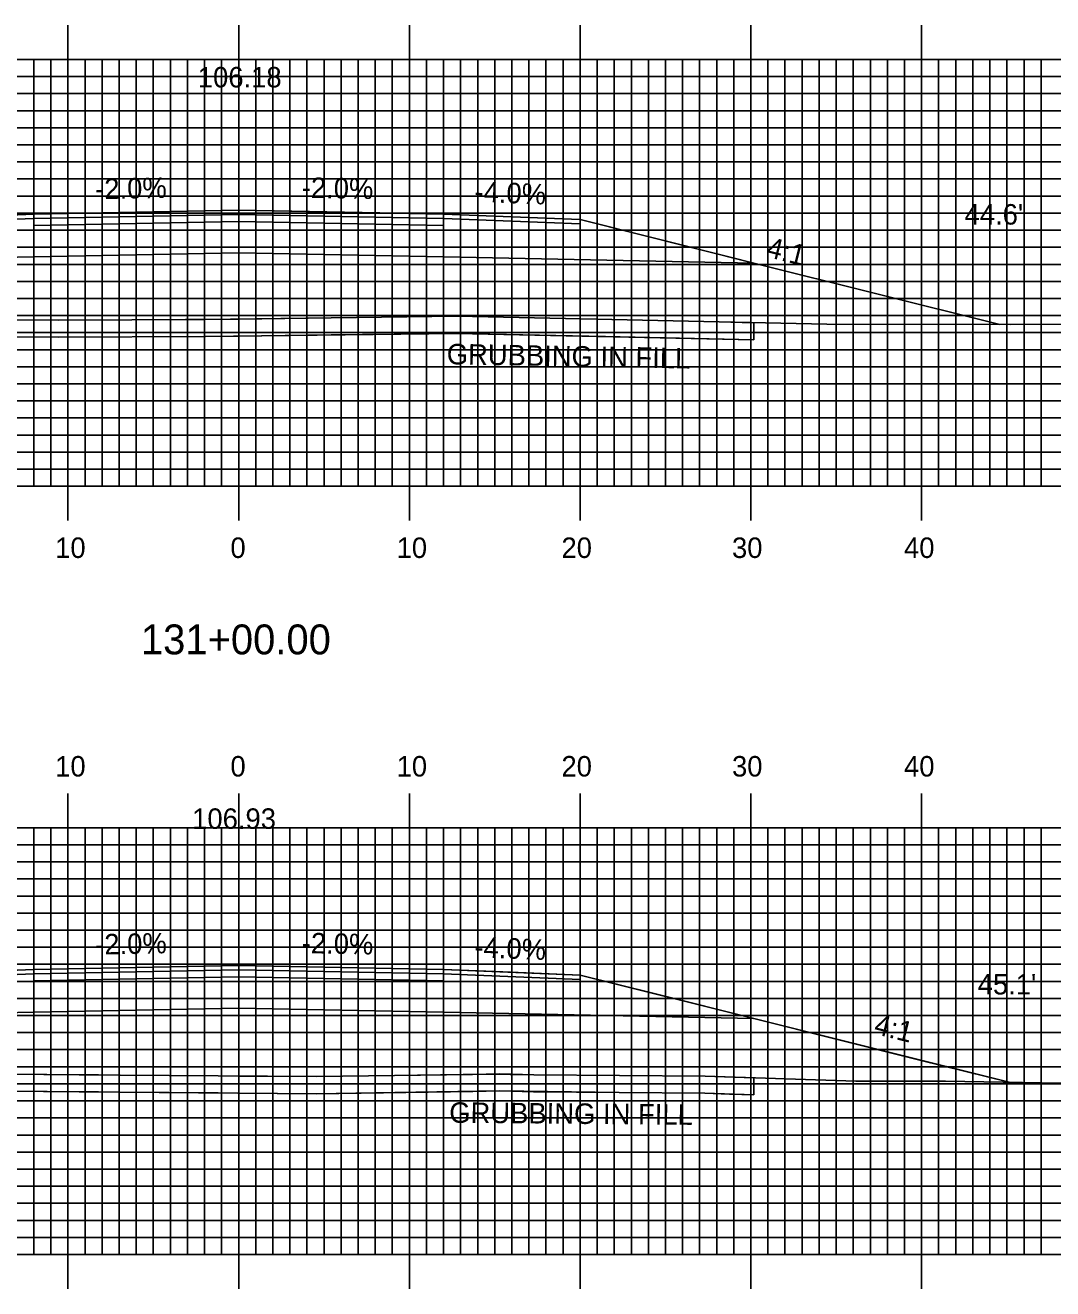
# Model space of a CAD drawing. Extents: x 1773990 to 1774333, y 442591 to 442811.
# Drawn here: x 1774143.2 to 1774203.3, y 442686.7 to 442760.7 of the extents above; entities that cross this region are included whole.
import ezdxf

# ---------------------------------------------------------------- set-up
doc = ezdxf.new("R2010")
doc.units = 0
for name, color, linetype in [('ANNOTATION', 7, 'Continuous'), ('D_Roadway_Centerline', 7, 'Continuous'), ('D_Roadway_Centerline_Text', 7, 'Continuous'), ('D_Roadway_Edge_Shoulder', 7, 'Continuous'), ('D_Roadway_Edge_TW', 7, 'Continuous'), ('D_Roadway_Pavement', 7, 'Continuous'), ('D_Roadway_SlopeLines', 7, 'Continuous'), ('D_Roadway_SubGrade', 7, 'Continuous'), ('D_Text_Standard', 7, 'Continuous'), ('GRUBBING IN FILL', 7, 'Continuous'), ('H_V ANNOTATION', 7, 'Continuous'), ('MAJOR', 7, 'Continuous'), ('MINOR', 7, 'Continuous'), ('S_Roadway_Centerline', 7, 'Continuous')]:
    doc.layers.add(name, color=color, linetype=linetype)

msp = doc.modelspace()

# ---------------------------------------------------------------- linework, layer by layer
at = {"layer": 'D_Roadway_Centerline'}
for points in [[(1774113.41, 442743.721), (1774123.659, 442746.284), (1774125.485, 442746.74), (1774135.659, 442749.284), (1774139.864, 442749.452), (1774143.659, 442749.604), (1774145.7, 442749.645), (1774155.657, 442749.844), (1774155.659, 442749.844), (1774164.958, 442749.658), (1774167.659, 442749.604), (1774175.659, 442749.284), (1774184.368, 442747.107), (1774185.833, 442746.74), (1774200.249, 442743.136)], [(1774112.312, 442699.568), (1774123.87, 442702.458), (1774133.89, 442704.963), (1774138.828, 442705.161), (1774143.659, 442705.354), (1774143.66, 442705.354), (1774155.659, 442705.594), (1774167.659, 442705.354), (1774171.137, 442705.215), (1774175.659, 442705.034), (1774180.146, 442703.912), (1774185.833, 442702.49), (1774195.567, 442700.056), (1774200.784, 442698.752)]]:
    msp.add_lwpolyline(points, dxfattribs=at)
at = {"layer": 'D_Roadway_Edge_Shoulder'}
for points in [[(1774143.659, 442749.604), (1774135.659, 442749.284), (1774135.659, 442749.034), (1774143.659, 442749.354)], [(1774167.659, 442749.604), (1774175.659, 442749.284), (1774175.659, 442749.034), (1774167.659, 442749.354)], [(1774143.659, 442705.354), (1774133.89, 442704.963), (1774133.89, 442704.713), (1774143.659, 442705.104)], [(1774167.659, 442705.354), (1774175.659, 442705.034), (1774175.659, 442704.784), (1774167.659, 442705.104)]]:
    msp.add_lwpolyline(points, close=True, dxfattribs=at)
at = {"layer": 'D_Roadway_Edge_TW'}
for points in [[(1774143.659, 442749.354), (1774143.659, 442749.604), (1774155.659, 442749.844), (1774167.659, 442749.604), (1774167.659, 442749.354), (1774155.659, 442749.594)], [(1774143.659, 442705.104), (1774143.659, 442705.354), (1774155.659, 442705.594), (1774167.659, 442705.354), (1774167.659, 442705.104), (1774155.659, 442705.344)]]:
    msp.add_lwpolyline(points, close=True, dxfattribs=at)
at = {"layer": 'D_Roadway_Pavement'}
for points in [[(1774143.659, 442748.937), (1774143.659, 442749.354), (1774155.659, 442749.594), (1774167.659, 442749.354), (1774167.659, 442748.937), (1774155.659, 442749.177)], [(1774143.659, 442704.687), (1774143.659, 442705.104), (1774155.659, 442705.344), (1774167.659, 442705.104), (1774167.659, 442704.687), (1774155.659, 442704.927)]]:
    msp.add_lwpolyline(points, close=True, dxfattribs=at)
at = {"layer": 'D_Roadway_SlopeLines'}
for points in [[(1774175.659, 442749.284), (1774185.833, 442746.74), (1774200.249, 442743.136)], [(1774175.659, 442705.034), (1774185.833, 442702.49), (1774200.784, 442698.752)]]:
    msp.add_lwpolyline(points, dxfattribs=at)
at = {"layer": 'D_Roadway_SubGrade'}
for points in [[(1774143.659, 442747.104), (1774125.485, 442746.74), (1774135.659, 442749.284), (1774135.659, 442749.034), (1774143.659, 442749.354), (1774155.659, 442749.594), (1774167.659, 442749.354), (1774175.659, 442749.034), (1774175.659, 442749.284), (1774185.833, 442746.74), (1774167.659, 442747.104), (1774155.659, 442747.344)], [(1774143.659, 442702.854), (1774123.87, 442702.458), (1774133.89, 442704.963), (1774133.89, 442704.713), (1774143.659, 442705.104), (1774155.659, 442705.344), (1774167.659, 442705.104), (1774175.659, 442704.784), (1774175.659, 442705.034), (1774185.833, 442702.49), (1774167.659, 442702.854), (1774155.659, 442703.094)]]:
    msp.add_lwpolyline(points, close=True, dxfattribs=at)
at = {"layer": 'GRUBBING IN FILL'}
for p, q in [((1774185.833, 442743.248), (1774185.833, 442742.248)), ((1774185.833, 442743.248), (1774185.833, 442742.248)), ((1774185.833, 442699.02), (1774185.833, 442698.019)), ((1774185.833, 442699.02), (1774185.833, 442698.019))]:
    msp.add_line(p, q, dxfattribs=at)
for points in [[(1774125.485, 442743.49), (1774130.474, 442743.468), (1774137.786, 442743.435), (1774145.098, 442743.402), (1774149.402, 442743.416), (1774155.659, 442743.456), (1774155.659, 442742.456), (1774153.713, 442742.43), (1774145.097, 442742.402), (1774135.291, 442742.446), (1774125.485, 442742.49)], [(1774125.485, 442743.49), (1774130.474, 442743.468), (1774137.786, 442743.435), (1774145.098, 442743.402), (1774149.402, 442743.416), (1774155.659, 442743.456), (1774155.659, 442742.456), (1774153.713, 442742.43), (1774145.097, 442742.402), (1774135.291, 442742.446), (1774125.485, 442742.49)], [(1774155.659, 442743.456), (1774161.077, 442743.527), (1774168.448, 442743.624), (1774172.978, 442743.526), (1774177.508, 442743.428), (1774183.813, 442743.292), (1774185.833, 442743.248), (1774185.833, 442742.248), (1774177.139, 442742.436), (1774168.444, 442742.624), (1774161.079, 442742.527), (1774155.659, 442742.456)], [(1774155.659, 442743.456), (1774161.077, 442743.527), (1774168.448, 442743.624), (1774172.978, 442743.526), (1774177.508, 442743.428), (1774183.813, 442743.292), (1774185.833, 442743.248), (1774185.833, 442742.248), (1774177.139, 442742.436), (1774168.444, 442742.624), (1774161.079, 442742.527), (1774155.659, 442742.456)], [(1774125.485, 442699.396), (1774135.923, 442699.291), (1774146.312, 442699.187), (1774148.708, 442699.175), (1774154.465, 442699.129), (1774155.659, 442699.119), (1774155.659, 442698.119), (1774154.463, 442698.129), (1774148.7, 442698.175), (1774135.896, 442698.291), (1774125.485, 442698.396)], [(1774155.659, 442699.119), (1774160.222, 442699.083), (1774164.789, 442699.15), (1774170.158, 442699.238), (1774172.955, 442699.185), (1774177.971, 442699.15), (1774182.987, 442699.114), (1774185.833, 442699.02), (1774185.833, 442698.019), (1774184.4, 442698.067), (1774182.967, 442698.114), (1774177.95, 442698.15), (1774170.955, 442698.257), (1774164.8, 442698.15), (1774160.225, 442698.083), (1774155.659, 442698.119)], [(1774155.659, 442699.119), (1774160.222, 442699.083), (1774164.789, 442699.15), (1774170.158, 442699.238), (1774172.955, 442699.185), (1774177.971, 442699.15), (1774182.987, 442699.114), (1774185.833, 442699.02), (1774185.833, 442698.019), (1774184.4, 442698.067), (1774182.967, 442698.114), (1774177.95, 442698.15), (1774170.955, 442698.257), (1774164.8, 442698.15), (1774160.225, 442698.083), (1774155.659, 442698.119)]]:
    msp.add_lwpolyline(points, close=True, dxfattribs=at)
for points in [[(1774125.485, 442742.49), (1774145.097, 442742.402), (1774153.713, 442742.43), (1774168.444, 442742.624), (1774185.833, 442742.248)], [(1774125.485, 442742.49), (1774145.097, 442742.402), (1774153.713, 442742.43), (1774168.444, 442742.624), (1774185.833, 442742.248)], [(1774125.485, 442699.396), (1774135.923, 442699.291), (1774146.312, 442699.187), (1774148.708, 442699.175), (1774154.465, 442699.129), (1774155.659, 442699.119), (1774155.659, 442698.119), (1774154.463, 442698.129), (1774148.7, 442698.175), (1774135.896, 442698.291), (1774125.485, 442698.396)], [(1774125.485, 442698.396), (1774146.307, 442698.187), (1774147.443, 442698.186), (1774148.7, 442698.175), (1774160.225, 442698.083), (1774169.375, 442698.218), (1774170.955, 442698.257), (1774172.934, 442698.185), (1774182.967, 442698.114), (1774185.833, 442698.019)], [(1774125.485, 442698.396), (1774146.307, 442698.187), (1774147.443, 442698.186), (1774148.7, 442698.175), (1774160.225, 442698.083), (1774169.375, 442698.218), (1774170.955, 442698.257), (1774172.934, 442698.185), (1774182.967, 442698.114), (1774185.833, 442698.019)]]:
    msp.add_lwpolyline(points, dxfattribs=at)
at = {"layer": 'MAJOR'}
for p, q in [((1774145.659, 442760.669), (1774145.659, 442758.665)), ((1774155.659, 442760.669), (1774155.659, 442758.665)), ((1774165.659, 442760.669), (1774165.659, 442758.665)), ((1774175.659, 442760.669), (1774175.659, 442758.665)), ((1774185.659, 442760.669), (1774185.659, 442758.665)), ((1774195.659, 442760.669), (1774195.659, 442758.665)), ((1774015.659, 442758.665), (1774295.659, 442758.665)), ((1774015.659, 442758.665), (1774295.659, 442758.665)), ((1774145.659, 442733.665), (1774145.659, 442758.665)), ((1774155.659, 442733.665), (1774155.659, 442758.665)), ((1774165.659, 442733.665), (1774165.659, 442758.665)), ((1774175.659, 442733.665), (1774175.659, 442758.665)), ((1774185.659, 442733.665), (1774185.659, 442758.665)), ((1774195.659, 442733.665), (1774195.659, 442758.665)), ((1774015.659, 442753.665), (1774295.659, 442753.665)), ((1774015.659, 442748.665), (1774295.659, 442748.665)), ((1774015.659, 442743.665), (1774295.659, 442743.665)), ((1774015.659, 442738.665), (1774295.659, 442738.665)), ((1774015.659, 442733.665), (1774295.659, 442733.665)), ((1774015.659, 442733.665), (1774295.659, 442733.665)), ((1774145.659, 442731.661), (1774145.659, 442733.665)), ((1774155.659, 442731.661), (1774155.659, 442733.665)), ((1774165.659, 442731.661), (1774165.659, 442733.665)), ((1774175.659, 442731.661), (1774175.659, 442733.665)), ((1774185.659, 442731.661), (1774185.659, 442733.665)), ((1774195.659, 442731.661), (1774195.659, 442733.665)), ((1774145.659, 442715.669), (1774145.659, 442713.665)), ((1774155.659, 442715.669), (1774155.659, 442713.665)), ((1774165.659, 442715.669), (1774165.659, 442713.665)), ((1774175.659, 442715.669), (1774175.659, 442713.665)), ((1774185.659, 442715.669), (1774185.659, 442713.665)), ((1774195.659, 442715.669), (1774195.659, 442713.665)), ((1774015.659, 442713.665), (1774295.659, 442713.665)), ((1774015.659, 442713.665), (1774295.659, 442713.665)), ((1774145.659, 442688.665), (1774145.659, 442713.665)), ((1774155.659, 442688.665), (1774155.659, 442713.665)), ((1774165.659, 442688.665), (1774165.659, 442713.665)), ((1774175.659, 442688.665), (1774175.659, 442713.665)), ((1774185.659, 442688.665), (1774185.659, 442713.665)), ((1774195.659, 442688.665), (1774195.659, 442713.665)), ((1774015.659, 442708.665), (1774295.659, 442708.665)), ((1774015.659, 442703.665), (1774295.659, 442703.665)), ((1774015.659, 442698.665), (1774295.659, 442698.665)), ((1774015.659, 442693.665), (1774295.659, 442693.665)), ((1774015.659, 442688.665), (1774295.659, 442688.665)), ((1774015.659, 442688.665), (1774295.659, 442688.665)), ((1774145.659, 442686.661), (1774145.659, 442688.665)), ((1774155.659, 442686.661), (1774155.659, 442688.665)), ((1774165.659, 442686.661), (1774165.659, 442688.665)), ((1774175.659, 442686.661), (1774175.659, 442688.665)), ((1774185.659, 442686.661), (1774185.659, 442688.665)), ((1774195.659, 442686.661), (1774195.659, 442688.665))]:
    msp.add_line(p, q, dxfattribs=at)
at = {"layer": 'MINOR'}
for p, q in [((1774143.659, 442733.665), (1774143.659, 442758.665)), ((1774144.659, 442733.665), (1774144.659, 442758.665)), ((1774146.659, 442733.665), (1774146.659, 442758.665)), ((1774147.659, 442733.665), (1774147.659, 442758.665)), ((1774148.659, 442733.665), (1774148.659, 442758.665)), ((1774149.659, 442733.665), (1774149.659, 442758.665)), ((1774150.659, 442733.665), (1774150.659, 442758.665)), ((1774151.659, 442733.665), (1774151.659, 442758.665)), ((1774152.659, 442733.665), (1774152.659, 442758.665)), ((1774153.659, 442733.665), (1774153.659, 442758.665)), ((1774154.659, 442733.665), (1774154.659, 442758.665)), ((1774156.659, 442733.665), (1774156.659, 442758.665)), ((1774157.659, 442733.665), (1774157.659, 442758.665)), ((1774158.659, 442733.665), (1774158.659, 442758.665)), ((1774159.659, 442733.665), (1774159.659, 442758.665)), ((1774160.659, 442733.665), (1774160.659, 442758.665)), ((1774161.659, 442733.665), (1774161.659, 442758.665)), ((1774162.659, 442733.665), (1774162.659, 442758.665)), ((1774163.659, 442733.665), (1774163.659, 442758.665)), ((1774164.659, 442733.665), (1774164.659, 442758.665)), ((1774166.659, 442733.665), (1774166.659, 442758.665)), ((1774167.659, 442733.665), (1774167.659, 442758.665)), ((1774168.659, 442733.665), (1774168.659, 442758.665)), ((1774169.659, 442733.665), (1774169.659, 442758.665)), ((1774170.659, 442733.665), (1774170.659, 442758.665)), ((1774171.659, 442733.665), (1774171.659, 442758.665)), ((1774172.659, 442733.665), (1774172.659, 442758.665)), ((1774173.659, 442733.665), (1774173.659, 442758.665)), ((1774174.659, 442733.665), (1774174.659, 442758.665)), ((1774176.659, 442733.665), (1774176.659, 442758.665)), ((1774177.659, 442733.665), (1774177.659, 442758.665)), ((1774178.659, 442733.665), (1774178.659, 442758.665)), ((1774179.659, 442733.665), (1774179.659, 442758.665)), ((1774180.659, 442733.665), (1774180.659, 442758.665)), ((1774181.659, 442733.665), (1774181.659, 442758.665)), ((1774182.659, 442733.665), (1774182.659, 442758.665)), ((1774183.659, 442733.665), (1774183.659, 442758.665)), ((1774184.659, 442733.665), (1774184.659, 442758.665)), ((1774186.659, 442733.665), (1774186.659, 442758.665)), ((1774187.659, 442733.665), (1774187.659, 442758.665)), ((1774188.659, 442733.665), (1774188.659, 442758.665)), ((1774189.659, 442733.665), (1774189.659, 442758.665)), ((1774190.659, 442733.665), (1774190.659, 442758.665)), ((1774191.659, 442733.665), (1774191.659, 442758.665)), ((1774192.659, 442733.665), (1774192.659, 442758.665)), ((1774193.659, 442733.665), (1774193.659, 442758.665)), ((1774194.659, 442733.665), (1774194.659, 442758.665)), ((1774196.659, 442733.665), (1774196.659, 442758.665)), ((1774197.659, 442733.665), (1774197.659, 442758.665)), ((1774198.659, 442733.665), (1774198.659, 442758.665)), ((1774199.659, 442733.665), (1774199.659, 442758.665)), ((1774200.659, 442733.665), (1774200.659, 442758.665)), ((1774201.659, 442733.665), (1774201.659, 442758.665)), ((1774202.659, 442733.665), (1774202.659, 442758.665)), ((1774015.659, 442757.665), (1774295.659, 442757.665)), ((1774015.659, 442756.665), (1774295.659, 442756.665)), ((1774015.659, 442755.665), (1774295.659, 442755.665)), ((1774015.659, 442754.665), (1774295.659, 442754.665)), ((1774015.659, 442752.665), (1774295.659, 442752.665)), ((1774015.659, 442751.665), (1774295.659, 442751.665)), ((1774015.659, 442750.665), (1774295.659, 442750.665)), ((1774015.659, 442749.665), (1774295.659, 442749.665)), ((1774015.659, 442747.665), (1774295.659, 442747.665)), ((1774015.659, 442746.665), (1774295.659, 442746.665)), ((1774015.659, 442745.665), (1774295.659, 442745.665)), ((1774015.659, 442744.665), (1774295.659, 442744.665)), ((1774015.659, 442742.665), (1774295.659, 442742.665)), ((1774015.659, 442741.665), (1774295.659, 442741.665)), ((1774015.659, 442740.665), (1774295.659, 442740.665)), ((1774015.659, 442739.665), (1774295.659, 442739.665)), ((1774015.659, 442737.665), (1774295.659, 442737.665)), ((1774015.659, 442736.665), (1774295.659, 442736.665)), ((1774015.659, 442735.665), (1774295.659, 442735.665)), ((1774015.659, 442734.665), (1774295.659, 442734.665)), ((1774143.659, 442688.665), (1774143.659, 442713.665)), ((1774144.659, 442688.665), (1774144.659, 442713.665)), ((1774146.659, 442688.665), (1774146.659, 442713.665)), ((1774147.659, 442688.665), (1774147.659, 442713.665)), ((1774148.659, 442688.665), (1774148.659, 442713.665)), ((1774149.659, 442688.665), (1774149.659, 442713.665)), ((1774150.659, 442688.665), (1774150.659, 442713.665)), ((1774151.659, 442688.665), (1774151.659, 442713.665)), ((1774152.659, 442688.665), (1774152.659, 442713.665)), ((1774153.659, 442688.665), (1774153.659, 442713.665)), ((1774154.659, 442688.665), (1774154.659, 442713.665)), ((1774156.659, 442688.665), (1774156.659, 442713.665)), ((1774157.659, 442688.665), (1774157.659, 442713.665)), ((1774158.659, 442688.665), (1774158.659, 442713.665)), ((1774159.659, 442688.665), (1774159.659, 442713.665)), ((1774160.659, 442688.665), (1774160.659, 442713.665)), ((1774161.659, 442688.665), (1774161.659, 442713.665)), ((1774162.659, 442688.665), (1774162.659, 442713.665)), ((1774163.659, 442688.665), (1774163.659, 442713.665)), ((1774164.659, 442688.665), (1774164.659, 442713.665)), ((1774166.659, 442688.665), (1774166.659, 442713.665)), ((1774167.659, 442688.665), (1774167.659, 442713.665)), ((1774168.659, 442688.665), (1774168.659, 442713.665)), ((1774169.659, 442688.665), (1774169.659, 442713.665)), ((1774170.659, 442688.665), (1774170.659, 442713.665)), ((1774171.659, 442688.665), (1774171.659, 442713.665)), ((1774172.659, 442688.665), (1774172.659, 442713.665)), ((1774173.659, 442688.665), (1774173.659, 442713.665)), ((1774174.659, 442688.665), (1774174.659, 442713.665)), ((1774176.659, 442688.665), (1774176.659, 442713.665)), ((1774177.659, 442688.665), (1774177.659, 442713.665)), ((1774178.659, 442688.665), (1774178.659, 442713.665)), ((1774179.659, 442688.665), (1774179.659, 442713.665)), ((1774180.659, 442688.665), (1774180.659, 442713.665)), ((1774181.659, 442688.665), (1774181.659, 442713.665)), ((1774182.659, 442688.665), (1774182.659, 442713.665)), ((1774183.659, 442688.665), (1774183.659, 442713.665)), ((1774184.659, 442688.665), (1774184.659, 442713.665)), ((1774186.659, 442688.665), (1774186.659, 442713.665)), ((1774187.659, 442688.665), (1774187.659, 442713.665)), ((1774188.659, 442688.665), (1774188.659, 442713.665)), ((1774189.659, 442688.665), (1774189.659, 442713.665)), ((1774190.659, 442688.665), (1774190.659, 442713.665)), ((1774191.659, 442688.665), (1774191.659, 442713.665)), ((1774192.659, 442688.665), (1774192.659, 442713.665)), ((1774193.659, 442688.665), (1774193.659, 442713.665)), ((1774194.659, 442688.665), (1774194.659, 442713.665)), ((1774196.659, 442688.665), (1774196.659, 442713.665)), ((1774197.659, 442688.665), (1774197.659, 442713.665)), ((1774198.659, 442688.665), (1774198.659, 442713.665)), ((1774199.659, 442688.665), (1774199.659, 442713.665)), ((1774200.659, 442688.665), (1774200.659, 442713.665)), ((1774201.659, 442688.665), (1774201.659, 442713.665)), ((1774202.659, 442688.665), (1774202.659, 442713.665)), ((1774015.659, 442712.665), (1774295.659, 442712.665)), ((1774015.659, 442711.665), (1774295.659, 442711.665)), ((1774015.659, 442710.665), (1774295.659, 442710.665)), ((1774015.659, 442709.665), (1774295.659, 442709.665)), ((1774015.659, 442707.665), (1774295.659, 442707.665)), ((1774015.659, 442706.665), (1774295.659, 442706.665)), ((1774015.659, 442705.665), (1774295.659, 442705.665)), ((1774015.659, 442704.665), (1774295.659, 442704.665)), ((1774015.659, 442702.665), (1774295.659, 442702.665)), ((1774015.659, 442701.665), (1774295.659, 442701.665)), ((1774015.659, 442700.665), (1774295.659, 442700.665)), ((1774015.659, 442699.665), (1774295.659, 442699.665)), ((1774015.659, 442697.665), (1774295.659, 442697.665)), ((1774015.659, 442696.665), (1774295.659, 442696.665)), ((1774015.659, 442695.665), (1774295.659, 442695.665)), ((1774015.659, 442694.665), (1774295.659, 442694.665)), ((1774015.659, 442692.665), (1774295.659, 442692.665)), ((1774015.659, 442691.665), (1774295.659, 442691.665)), ((1774015.659, 442690.665), (1774295.659, 442690.665)), ((1774015.659, 442689.665), (1774295.659, 442689.665))]:
    msp.add_line(p, q, dxfattribs=at)
at = {"layer": 'S_Roadway_Centerline'}
for points in [[(1774015.659, 442746.914), (1774021.875, 442746.854), (1774032.904, 442746.671), (1774034.207, 442746.662), (1774035.508, 442746.663), (1774045.562, 442746.752), (1774054.116, 442746.226), (1774059.287, 442746.02), (1774078.992, 442745.503), (1774080.613, 442745.485), (1774082.548, 442745.428), (1774091.734, 442745.312), (1774101.032, 442744.283), (1774103.519, 442744.031), (1774106.112, 442743.902), (1774122.137, 442743.506), (1774130.474, 442743.468), (1774145.098, 442743.402), (1774153.705, 442743.43), (1774168.448, 442743.624), (1774177.508, 442743.428), (1774190.118, 442743.156), (1774200.849, 442743.135), (1774211.65, 442743.192)], [(1774090.142, 442700.311), (1774100.842, 442700.131), (1774102.018, 442700.106), (1774113.135, 442699.525), (1774124.173, 442699.411), (1774124.306, 442699.408), (1774125.534, 442699.396), (1774146.312, 442699.187), (1774147.448, 442699.186), (1774148.708, 442699.175), (1774160.222, 442699.083), (1774169.356, 442699.218), (1774170.96, 442699.257), (1774172.955, 442699.185), (1774182.987, 442699.114), (1774191.809, 442698.821), (1774195.172, 442698.825), (1774197.059, 442698.815), (1774217.324, 442698.473)]]:
    msp.add_lwpolyline(points, dxfattribs=at)

# ---------------------------------------------------------------- texts
at = {"layer": 'ANNOTATION'}
for s, rotation, p in [('-2.0%', 1.14572, (1774147.264, 442750.477)), ('-2.0%', 358.85424, (1774159.345, 442750.571)), ('-4.0%', 357.70947, (1774169.451, 442750.334)), ('4:1', 345.96131, (1774186.51, 442747.118)), ('-2.0%', 1.14574, (1774147.266, 442706.227)), ('-2.0%', 358.85423, (1774159.345, 442706.321)), ('-4.0%', 357.70943, (1774169.451, 442706.084)), ('4:1', 345.96286, (1774192.814, 442701.606))]:
    msp.add_text(s, height=1.2, rotation=rotation, dxfattribs=at).set_placement(p)
at = {"layer": 'D_Roadway_Centerline'}
for s, p in [('C', (1774155.654, 442749.844)), ('L', (1774155.659, 442749.837)), ('C', (1774155.654, 442705.594)), ('L', (1774155.659, 442705.587))]:
    msp.add_text(s, height=0.0146, dxfattribs=at).set_placement(p)
at = {"layer": 'D_Roadway_Centerline_Text'}
for s, p in [('106.18', (1774153.267, 442757.029)), ('106.93', (1774152.935, 442713.598))]:
    msp.add_text(s, height=1.2, dxfattribs=at).set_placement(p)
at = {"layer": 'D_Text_Standard'}
for s, p in [("44.6'", (1774198.179, 442748.994)), ("45.1'", (1774198.947, 442703.897))]:
    msp.add_text(s, height=1.2, dxfattribs=at).set_placement(p)
at = {"layer": 'GRUBBING IN FILL'}
for rotation, p in [(358.9728, (1774167.838, 442740.817)), (359.49713, (1774167.989, 442696.384))]:
    msp.add_text('GRUBBING IN FILL', height=1.2, rotation=rotation, dxfattribs=at).set_placement(p)
at = {"layer": 'H_V ANNOTATION'}
for s, height, p in [('10', 1.2, (1774144.91, 442729.465)), ('0', 1.2, (1774155.177, 442729.465)), ('10', 1.2, (1774164.91, 442729.465)), ('20', 1.2, (1774174.567, 442729.465)), ('30', 1.2, (1774184.556, 442729.465)), ('40', 1.2, (1774194.631, 442729.465)), ('131+00.00', 1.75, (1774149.932, 442723.821)), ('10', 1.2, (1774144.91, 442716.665)), ('0', 1.2, (1774155.177, 442716.665)), ('10', 1.2, (1774164.91, 442716.665)), ('20', 1.2, (1774174.567, 442716.665)), ('30', 1.2, (1774184.556, 442716.665)), ('40', 1.2, (1774194.631, 442716.665))]:
    msp.add_text(s, height=height, dxfattribs=at).set_placement(p)

doc.saveas('drawing.dxf')
